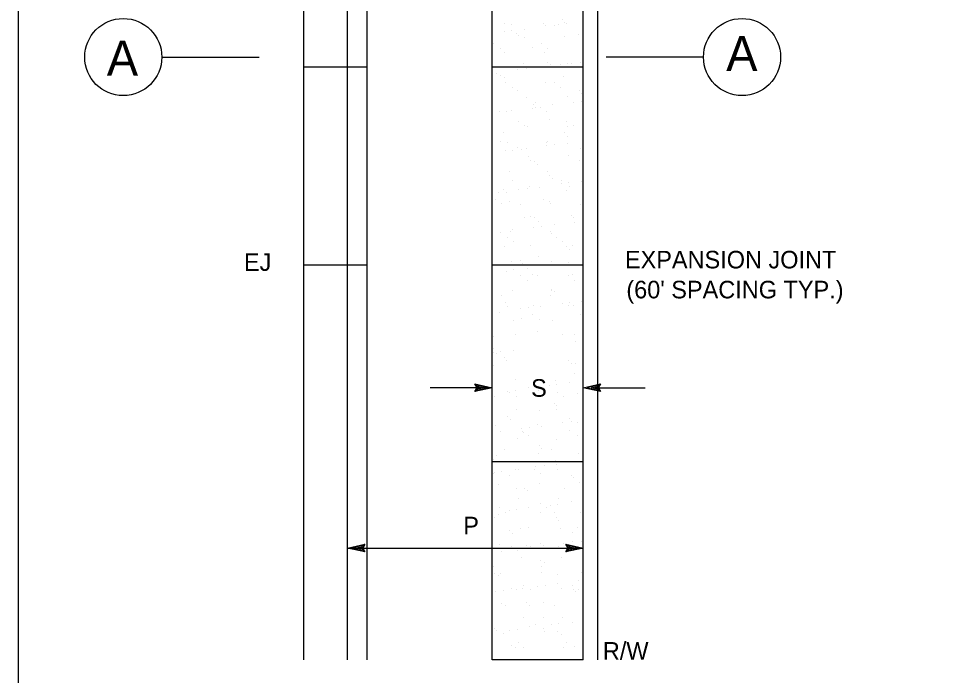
# Model space of a CAD drawing. Extents: x -118779 to -116979, y -104389 to -102939.
# Drawn here: x -118779.4 to -118463.7, y -103797.3 to -103572.9 of the extents above; entities that cross this region are included whole.
import ezdxf

# ---------------------------------------------------------------- set-up
doc = ezdxf.new("R2010")
doc.units = 0
for name, color, linetype in [('Default', 7, 'Continuous'), ('G-MARK', 7, 'Continuous'), ('G-TEXT', 7, 'Continuous'), ('Misc CnstDet(22)', 7, 'Continuous')]:
    doc.layers.add(name, color=color, linetype=linetype)

msp = doc.modelspace()

# ---------------------------------------------------------------- linework, layer by layer
at = {"layer": 'Default'}
msp.add_lwpolyline([(-118779.39, -102939.25), (-116979.39, -102939.25), (-116979.39, -104389.25), (-118779.39, -104389.25)], close=True, dxfattribs=at)
at = {"layer": 'G-MARK'}
for p, q in [((-118730.4, -103586.19), (-118697.22, -103586.19)), ((-118545.41, -103586.19), (-118578.59, -103586.19)), ((-118617.58, -103699.01), (-118638.74, -103699.01)), ((-118581.5, -103699.01), (-118565.32, -103699.01)), ((-118666.94, -103753.76), (-118586.48, -103753.76))]:
    msp.add_line(p, q, dxfattribs=at)
for centre in [(-118743.6, -103586.11), (-118532.21, -103586.11)]:
    msp.add_circle(centre, 13.17, dxfattribs=at)
at = {"layer": 'G-TEXT'}
for points in [[(-118623.49, -103697.69), (-118617.58, -103699.01), (-118623.49, -103700.32), (-118623.28, -103699.97), (-118618.95, -103699.01), (-118623.28, -103698.04), (-118623.07, -103698.39), (-118620.3, -103699.01), (-118623.07, -103699.62), (-118622.86, -103699.27), (-118621.66, -103699.01), (-118622.86, -103698.74), (-118622.7, -103699.01), (-118623.49, -103700.32), (-118622.7, -103699.01)], [(-118580.57, -103700.33), (-118586.48, -103699.01), (-118580.57, -103697.7), (-118580.78, -103698.05), (-118585.11, -103699.01), (-118580.78, -103699.98), (-118580.99, -103699.63), (-118583.76, -103699.01), (-118580.99, -103698.4), (-118581.2, -103698.75), (-118582.4, -103699.01), (-118581.2, -103699.28), (-118581.36, -103699.01), (-118580.57, -103697.7), (-118581.36, -103699.01)], [(-118661.03, -103755.08), (-118666.94, -103753.76), (-118661.03, -103752.45), (-118661.24, -103752.8), (-118665.57, -103753.76), (-118661.24, -103754.73), (-118661.45, -103754.38), (-118664.22, -103753.76), (-118661.45, -103753.15), (-118661.66, -103753.5), (-118662.86, -103753.76), (-118661.66, -103754.03), (-118661.82, -103753.76), (-118661.03, -103752.45), (-118661.82, -103753.76)], [(-118592.38, -103752.44), (-118586.48, -103753.76), (-118592.38, -103755.07), (-118592.17, -103754.72), (-118587.84, -103753.76), (-118592.17, -103752.79), (-118591.96, -103753.14), (-118589.19, -103753.76), (-118591.96, -103754.37), (-118591.75, -103754.02), (-118590.55, -103753.76), (-118591.76, -103753.49), (-118591.59, -103753.76), (-118592.38, -103755.07), (-118591.59, -103753.76)]]:
    msp.add_lwpolyline(points, close=True, dxfattribs=at)
at = {"layer": 'Misc CnstDet(22)'}
for p, q in [((-118593.53, -103573.34), (-118593.53, -103573.34)), ((-118613.43, -103574.58), (-118613.43, -103574.58)), ((-118610.95, -103575), (-118610.95, -103575)), ((-118606.38, -103576.66), (-118606.38, -103576.66)), ((-118600.16, -103574.58), (-118600.16, -103574.58)), ((-118599.33, -103575.41), (-118599.33, -103575.41)), ((-118596.43, -103575.41), (-118596.43, -103575.41)), ((-118594.77, -103575), (-118594.77, -103575)), ((-118592.7, -103574.17), (-118592.7, -103574.17)), ((-118592.28, -103574.58), (-118592.28, -103574.58)), ((-118613.43, -103577.48), (-118613.43, -103577.48)), ((-118610.95, -103577.07), (-118610.95, -103577.07)), ((-118609.29, -103577.9), (-118609.29, -103577.9)), ((-118608.46, -103578.73), (-118608.46, -103578.73)), ((-118606.38, -103579.56), (-118606.38, -103579.56)), ((-118592.7, -103579.14), (-118592.7, -103579.14)), ((-118588.13, -103578.31), (-118588.13, -103578.31)), ((-118617.17, -103581.63), (-118617.17, -103581.63)), ((-118603.9, -103582.88), (-118603.9, -103582.88)), ((-118600.58, -103581.63), (-118600.58, -103581.63)), ((-118614.68, -103583.29), (-118614.68, -103583.29)), ((-118613.43, -103584.54), (-118613.43, -103584.54)), ((-118599.75, -103584.54), (-118599.75, -103584.54)), ((-118598.5, -103583.29), (-118598.5, -103583.29)), ((-118606.8, -103588.27), (-118606.8, -103588.27)), ((-118598.5, -103587.85), (-118598.5, -103587.85)), ((-118597.67, -103588.68), (-118597.67, -103588.68)), ((-118594.36, -103588.68), (-118594.36, -103588.68)), ((-118591.87, -103588.27), (-118591.87, -103588.27)), ((-118590.62, -103588.27), (-118590.62, -103588.27)), ((-118587.3, -103587.85), (-118587.3, -103587.85)), ((-118660.3, -103589.51), (-118681.87, -103589.51)), ((-118586.48, -103589.51), (-118617.58, -103589.51)), ((-118615.92, -103591.59), (-118615.92, -103591.59)), ((-118614.68, -103592.42), (-118614.68, -103592.42)), ((-118608.87, -103590.34), (-118608.87, -103590.34)), ((-118605.97, -103589.51), (-118605.97, -103589.51)), ((-118605.97, -103589.93), (-118605.97, -103589.93)), ((-118601.82, -103589.51), (-118601.82, -103589.51)), ((-118592.28, -103589.51), (-118592.28, -103589.51)), ((-118613.43, -103593.25), (-118613.43, -103593.25)), ((-118613.02, -103594.9), (-118613.02, -103594.9)), ((-118613.02, -103594.9), (-118613.02, -103594.9)), ((-118599.33, -103594.9), (-118599.33, -103594.9)), ((-118596.43, -103594.9), (-118596.43, -103594.9)), ((-118593.11, -103592.83), (-118593.11, -103592.83)), ((-118610.53, -103596.56), (-118610.53, -103596.56)), ((-118608.87, -103597.39), (-118608.87, -103597.39)), ((-118594.36, -103596.56), (-118594.36, -103596.56)), ((-118587.72, -103597.39), (-118587.72, -103597.39)), ((-118586.89, -103598.64), (-118586.89, -103598.64)), ((-118605.97, -103599.88), (-118605.97, -103599.88)), ((-118602.65, -103601.54), (-118602.65, -103601.54)), ((-118591.87, -103599.47), (-118591.87, -103599.47)), ((-118589.79, -103601.54), (-118589.79, -103601.54)), ((-118586.89, -103601.13), (-118586.89, -103601.13)), ((-118615.09, -103604.86), (-118615.09, -103604.86)), ((-118612.61, -103604.86), (-118612.61, -103604.86)), ((-118610.95, -103604.44), (-118610.95, -103604.44)), ((-118603.9, -103603.61), (-118603.9, -103603.61)), ((-118603.48, -103602.37), (-118603.48, -103602.37)), ((-118602.65, -103603.2), (-118602.65, -103603.2)), ((-118600.99, -103603.2), (-118600.99, -103603.2)), ((-118598.92, -103604.86), (-118598.92, -103604.86)), ((-118596.84, -103602.37), (-118596.84, -103602.37)), ((-118608.46, -103608.18), (-118608.46, -103608.18)), ((-118598.09, -103607.35), (-118598.09, -103607.35)), ((-118592.28, -103608.18), (-118592.28, -103608.18)), ((-118606.38, -103609.42), (-118606.38, -103609.42)), ((-118605.55, -103609.84), (-118605.55, -103609.84)), ((-118591.87, -103609.84), (-118591.87, -103609.84)), ((-118589.79, -103609.42), (-118589.79, -103609.42)), ((-118613.85, -103611.91), (-118613.85, -103611.91)), ((-118592.7, -103611.91), (-118592.7, -103611.91)), ((-118591.87, -103613.15), (-118591.87, -103613.15)), ((-118614.68, -103614.81), (-118614.68, -103614.81)), ((-118612.19, -103615.23), (-118612.19, -103615.23)), ((-118608.87, -103616.89), (-118608.87, -103616.89)), ((-118607.63, -103617.72), (-118607.63, -103617.72)), ((-118605.97, -103617.3), (-118605.97, -103617.3)), ((-118598.92, -103615.23), (-118598.92, -103615.23)), ((-118598.92, -103616.47), (-118598.92, -103616.47)), ((-118598.5, -103614.81), (-118598.5, -103614.81)), ((-118596.43, -103616.06), (-118596.43, -103616.06)), ((-118591.87, -103615.64), (-118591.87, -103615.64)), ((-118587.3, -103617.3), (-118587.3, -103617.3)), ((-118613.02, -103618.13), (-118613.02, -103618.13)), ((-118610.53, -103618.13), (-118610.53, -103618.13)), ((-118605.14, -103620.21), (-118605.14, -103620.21)), ((-118591.45, -103619.79), (-118591.45, -103619.79)), ((-118604.31, -103621.45), (-118604.31, -103621.45)), ((-118603.07, -103621.86), (-118603.07, -103621.86)), ((-118602.24, -103622.69), (-118602.24, -103622.69)), ((-118587.72, -103621.45), (-118587.72, -103621.45)), ((-118611.78, -103625.18), (-118611.78, -103625.18)), ((-118598.5, -103625.18), (-118598.5, -103625.18)), ((-118598.09, -103626.43), (-118598.09, -103626.43)), ((-118610.53, -103628.09), (-118610.53, -103628.09)), ((-118604.72, -103630.16), (-118604.72, -103630.16)), ((-118596.84, -103627.67), (-118596.84, -103627.67)), ((-118593.94, -103628.09), (-118593.94, -103628.09)), ((-118593.94, -103629.33), (-118593.94, -103629.33)), ((-118591.45, -103628.92), (-118591.45, -103628.92)), ((-118591.04, -103630.16), (-118591.04, -103630.16)), ((-118586.89, -103628.5), (-118586.89, -103628.5)), ((-118615.51, -103632.23), (-118615.51, -103632.23)), ((-118613.85, -103631.4), (-118613.85, -103631.4)), ((-118612.61, -103632.23), (-118612.61, -103632.23)), ((-118608.46, -103631.4), (-118608.46, -103631.4)), ((-118605.55, -103630.99), (-118605.55, -103630.99)), ((-118601.41, -103630.57), (-118601.41, -103630.57)), ((-118592.28, -103631.82), (-118592.28, -103631.82)), ((-118616.34, -103634.72), (-118616.34, -103634.72)), ((-118614.26, -103635.97), (-118614.26, -103635.97)), ((-118611.78, -103635.55), (-118611.78, -103635.55)), ((-118608.04, -103636.38), (-118608.04, -103636.38)), ((-118600.16, -103634.72), (-118600.16, -103634.72)), ((-118598.09, -103635.55), (-118598.09, -103635.55)), ((-118597.67, -103635.97), (-118597.67, -103635.97)), ((-118587.3, -103636.38), (-118587.3, -103636.38)), ((-118606.38, -103640.94), (-118606.38, -103640.94)), ((-118604.31, -103640.53), (-118604.31, -103640.53)), ((-118603.07, -103640.94), (-118603.07, -103640.94)), ((-118601.82, -103642.19), (-118601.82, -103642.19)), ((-118590.62, -103640.11), (-118590.62, -103640.11)), ((-118589.79, -103640.94), (-118589.79, -103640.94)), ((-118589.38, -103642.6), (-118589.38, -103642.6)), ((-118586.48, -103642.19), (-118586.48, -103642.19)), ((-118614.68, -103645.92), (-118614.68, -103645.92)), ((-118611.36, -103645.51), (-118611.36, -103645.51)), ((-118610.53, -103645.09), (-118610.53, -103645.09)), ((-118603.48, -103644.26), (-118603.48, -103644.26)), ((-118600.58, -103643.85), (-118600.58, -103643.85)), ((-118597.67, -103645.51), (-118597.67, -103645.51)), ((-118596.43, -103643.43), (-118596.43, -103643.43)), ((-118612.19, -103647.58), (-118612.19, -103647.58)), ((-118610.12, -103649.24), (-118610.12, -103649.24)), ((-118597.26, -103646.34), (-118597.26, -103646.34)), ((-118595.6, -103647.58), (-118595.6, -103647.58)), ((-118593.53, -103649.24), (-118593.53, -103649.24)), ((-118613.43, -103650.9), (-118613.43, -103650.9)), ((-118604.31, -103650.48), (-118604.31, -103650.48)), ((-118592.28, -103650.9), (-118592.28, -103650.9)), ((-118591.04, -103651.73), (-118591.04, -103651.73)), ((-118590.21, -103650.48), (-118590.21, -103650.48)), ((-118608.04, -103655.46), (-118608.04, -103655.46)), ((-118601.82, -103654.22), (-118601.82, -103654.22)), ((-118660.3, -103657.12), (-118681.87, -103657.12)), ((-118586.48, -103657.12), (-118617.58, -103657.12)), ((-118610.95, -103655.87), (-118610.95, -103655.87)), ((-118610.12, -103658.78), (-118610.12, -103658.78)), ((-118607.21, -103656.7), (-118607.21, -103656.7)), ((-118605.55, -103658.36), (-118605.55, -103658.36)), ((-118598.5, -103657.12), (-118598.5, -103657.12)), ((-118597.26, -103655.87), (-118597.26, -103655.87)), ((-118596.01, -103657.12), (-118596.01, -103657.12)), ((-118591.45, -103656.29), (-118591.45, -103656.29)), ((-118586.48, -103656.29), (-118586.48, -103656.29)), ((-118612.61, -103659.19), (-118612.61, -103659.19)), ((-118608.04, -103660.85), (-118608.04, -103660.85)), ((-118603.9, -103660.44), (-118603.9, -103660.44)), ((-118602.24, -103660.85), (-118602.24, -103660.85)), ((-118591.45, -103660.85), (-118591.45, -103660.85)), ((-118590.21, -103660.44), (-118590.21, -103660.44)), ((-118605.55, -103662.51), (-118605.55, -103662.51)), ((-118589.38, -103662.51), (-118589.38, -103662.51)), ((-118614.26, -103667.49), (-118614.26, -103667.49)), ((-118610.53, -103665.83), (-118610.53, -103665.83)), ((-118597.67, -103667.49), (-118597.67, -103667.49)), ((-118597.26, -103665.41), (-118597.26, -103665.41)), ((-118597.26, -103665.83), (-118597.26, -103665.83)), ((-118596.43, -103666.24), (-118596.43, -103666.24)), ((-118613.02, -103669.98), (-118613.02, -103669.98)), ((-118612.19, -103671.22), (-118612.19, -103671.22)), ((-118603.48, -103670.81), (-118603.48, -103670.81)), ((-118600.99, -103671.22), (-118600.99, -103671.22)), ((-118593.53, -103670.39), (-118593.53, -103670.39)), ((-118591.45, -103670.81), (-118591.45, -103670.81)), ((-118591.04, -103669.98), (-118591.04, -103669.98)), ((-118589.79, -103670.81), (-118589.79, -103670.81)), ((-118586.89, -103669.56), (-118586.89, -103669.56)), ((-118615.09, -103673.29), (-118615.09, -103673.29)), ((-118608.04, -103672.05), (-118608.04, -103672.05)), ((-118605.14, -103671.64), (-118605.14, -103671.64)), ((-118603.9, -103674.12), (-118603.9, -103674.12)), ((-118587.3, -103674.12), (-118587.3, -103674.12)), ((-118610.12, -103676.2), (-118610.12, -103676.2)), ((-118607.63, -103675.37), (-118607.63, -103675.37)), ((-118601.41, -103675.78), (-118601.41, -103675.78)), ((-118596.84, -103676.2), (-118596.84, -103676.2)), ((-118586.48, -103675.37), (-118586.48, -103675.37)), ((-118609.7, -103680.76), (-118609.7, -103680.76)), ((-118602.24, -103679.93), (-118602.24, -103679.93)), ((-118593.53, -103680.76), (-118593.53, -103680.76)), ((-118589.38, -103680.76), (-118589.38, -103680.76)), ((-118617.17, -103681.59), (-118617.17, -103681.59)), ((-118588.96, -103683.25), (-118588.96, -103683.25)), ((-118617.17, -103685.74), (-118617.17, -103685.74)), ((-118617.17, -103686.98), (-118617.17, -103686.98)), ((-118614.68, -103686.57), (-118614.68, -103686.57)), ((-118610.12, -103686.15), (-118610.12, -103686.15)), ((-118610.12, -103686.15), (-118610.12, -103686.15)), ((-118617.58, -103697.35), (-118617.58, -103688.23)), ((-118615.92, -103687.4), (-118615.92, -103687.4)), ((-118613.43, -103688.64), (-118613.43, -103688.64)), ((-118612.61, -103689.89), (-118612.61, -103689.89)), ((-118591.45, -103689.89), (-118591.45, -103689.89)), ((-118586.48, -103697.35), (-118586.48, -103688.23)), ((-118617.17, -103691.54), (-118617.17, -103691.54)), ((-118590.62, -103690.72), (-118590.62, -103690.72)), ((-118588.96, -103690.72), (-118588.96, -103690.72)), ((-118609.7, -103696.11), (-118609.7, -103696.11)), ((-118596.01, -103696.52), (-118596.01, -103696.52)), ((-118589.38, -103694.03), (-118589.38, -103694.03)), ((-118609.7, -103699.84), (-118609.7, -103699.84)), ((-118605.14, -103699.01), (-118605.14, -103699.01)), ((-118601.82, -103699.84), (-118601.82, -103699.84)), ((-118598.09, -103698.18), (-118598.09, -103698.18)), ((-118595.6, -103697.77), (-118595.6, -103697.77)), ((-118591.04, -103697.35), (-118591.04, -103697.35)), ((-118586.48, -103699.01), (-118586.48, -103699.01)), ((-118617.58, -103701.08), (-118617.58, -103701.08)), ((-118616.75, -103701.91), (-118616.75, -103701.91)), ((-118612.19, -103700.25), (-118612.19, -103700.25)), ((-118611.78, -103700.67), (-118611.78, -103700.67)), ((-118609.29, -103701.91), (-118609.29, -103701.91)), ((-118602.65, -103701.08), (-118602.65, -103701.08)), ((-118595.19, -103700.67), (-118595.19, -103700.67)), ((-118593.11, -103701.91), (-118593.11, -103701.91)), ((-118588.55, -103701.08), (-118588.55, -103701.08)), ((-118586.48, -103701.08), (-118586.48, -103701.08)), ((-118617.58, -103704.4), (-118617.58, -103704.4)), ((-118596.43, -103704.4), (-118596.43, -103704.4)), ((-118595.6, -103705.23), (-118595.6, -103705.23)), ((-118612.19, -103708.96), (-118612.19, -103708.96)), ((-118609.29, -103706.48), (-118609.29, -103706.48)), ((-118601.41, -103706.89), (-118601.41, -103706.89)), ((-118595.6, -103706.48), (-118595.6, -103706.48)), ((-118591.04, -103709.38), (-118591.04, -103709.38)), ((-118616.34, -103711.87), (-118616.34, -103711.87)), ((-118611.36, -103709.79), (-118611.36, -103709.79)), ((-118602.24, -103711.45), (-118602.24, -103711.45)), ((-118600.58, -103712.28), (-118600.58, -103712.28)), ((-118593.53, -103711.04), (-118593.53, -103711.04)), ((-118590.62, -103710.62), (-118590.62, -103710.62)), ((-118588.55, -103711.04), (-118588.55, -103711.04)), ((-118586.48, -103710.21), (-118586.48, -103710.21)), ((-118614.68, -103713.94), (-118614.68, -103713.94)), ((-118607.63, -103713.11), (-118607.63, -103713.11)), ((-118607.21, -103713.94), (-118607.21, -103713.94)), ((-118606.8, -103714.36), (-118606.8, -103714.36)), ((-118605.14, -103715.19), (-118605.14, -103715.19)), ((-118604.72, -103712.7), (-118604.72, -103712.7)), ((-118591.04, -103713.53), (-118591.04, -103713.53)), ((-118588.55, -103715.19), (-118588.55, -103715.19)), ((-118608.87, -103716.43), (-118608.87, -103716.43)), ((-118595.6, -103716.85), (-118595.6, -103716.85)), ((-118613.43, -103720.16), (-118613.43, -103720.16)), ((-118601.82, -103721.41), (-118601.82, -103721.41)), ((-118601.41, -103718.92), (-118601.41, -103718.92)), ((-118600.58, -103719.75), (-118600.58, -103719.75)), ((-118597.26, -103720.16), (-118597.26, -103720.16)), ((-118588.13, -103721.41), (-118588.13, -103721.41)), ((-118586.48, -103724.31), (-118617.58, -103724.31)), ((-118617.17, -103723.48), (-118617.17, -103723.48)), ((-118616.34, -103724.31), (-118616.34, -103724.31)), ((-118615.92, -103722.24), (-118615.92, -103722.24)), ((-118596.01, -103723.9), (-118596.01, -103723.9)), ((-118595.6, -103725.14), (-118595.6, -103725.14)), ((-118588.55, -103724.31), (-118588.55, -103724.31)), ((-118616.75, -103728.04), (-118616.75, -103728.04)), ((-118614.26, -103727.63), (-118614.26, -103727.63)), ((-118609.7, -103726.8), (-118609.7, -103726.8)), ((-118608.46, -103726.8), (-118608.46, -103726.8)), ((-118603.07, -103726.8), (-118603.07, -103726.8)), ((-118602.65, -103725.97), (-118602.65, -103725.97)), ((-118599.75, -103725.56), (-118599.75, -103725.56)), ((-118595.19, -103726.8), (-118595.19, -103726.8)), ((-118586.48, -103726.8), (-118586.48, -103726.8)), ((-118617.17, -103728.46), (-118617.17, -103728.46)), ((-118611.78, -103728.87), (-118611.78, -103728.87)), ((-118600.99, -103728.46), (-118600.99, -103728.46)), ((-118590.62, -103728.87), (-118590.62, -103728.87)), ((-118589.79, -103729.7), (-118589.79, -103729.7)), ((-118587.72, -103731.36), (-118587.72, -103731.36)), ((-118615.51, -103732.19), (-118615.51, -103732.19)), ((-118609.29, -103733.44), (-118609.29, -103733.44)), ((-118606.38, -103733.44), (-118606.38, -103733.44)), ((-118605.55, -103734.27), (-118605.55, -103734.27)), ((-118601.41, -103731.78), (-118601.41, -103731.78)), ((-118592.7, -103733.44), (-118592.7, -103733.44)), ((-118608.46, -103736.75), (-118608.46, -103736.75)), ((-118594.77, -103736.75), (-118594.77, -103736.75)), ((-118615.09, -103740.07), (-118615.09, -103740.07)), ((-118611.78, -103740.9), (-118611.78, -103740.9)), ((-118609.29, -103740.49), (-118609.29, -103740.49)), ((-118605.14, -103740.07), (-118605.14, -103740.07)), ((-118600.99, -103738.41), (-118600.99, -103738.41)), ((-118598.92, -103740.07), (-118598.92, -103740.07)), ((-118597.67, -103739.24), (-118597.67, -103739.24)), ((-118595.19, -103738.83), (-118595.19, -103738.83)), ((-118590.62, -103738), (-118590.62, -103738)), ((-118666.94, -103752.93), (-118666.94, -103743.39)), ((-118616.75, -103743.39), (-118616.75, -103743.39)), ((-118615.51, -103742.15), (-118615.51, -103742.15)), ((-118613.02, -103741.73), (-118613.02, -103741.73)), ((-118600.99, -103741.73), (-118600.99, -103741.73)), ((-118596.43, -103741.73), (-118596.43, -103741.73)), ((-118595.6, -103743.39), (-118595.6, -103743.39)), ((-118587.3, -103741.73), (-118587.3, -103741.73)), ((-118586.48, -103752.93), (-118586.48, -103743.39)), ((-118608.04, -103747.12), (-118608.04, -103747.12)), ((-118605.14, -103746.71), (-118605.14, -103746.71)), ((-118594.77, -103744.22), (-118594.77, -103744.22)), ((-118594.36, -103747.12), (-118594.36, -103747.12)), ((-118588.55, -103746.71), (-118588.55, -103746.71)), ((-118611.78, -103747.95), (-118611.78, -103747.95)), ((-118610.53, -103748.78), (-118610.53, -103748.78)), ((-118590.21, -103748.37), (-118590.21, -103748.37)), ((-118615.09, -103752.51), (-118615.09, -103752.51)), ((-118610.95, -103753.34), (-118610.95, -103753.34)), ((-118605.97, -103752.93), (-118605.97, -103752.93)), ((-118604.31, -103753.34), (-118604.31, -103753.34)), ((-118600.99, -103752.1), (-118600.99, -103752.1)), ((-118600.16, -103752.93), (-118600.16, -103752.93)), ((-118594.77, -103753.34), (-118594.77, -103753.34)), ((-118593.11, -103752.1), (-118593.11, -103752.1)), ((-118590.21, -103751.69), (-118590.21, -103751.69)), ((-118586.89, -103751.69), (-118586.89, -103751.69)), ((-118666.94, -103756.66), (-118666.94, -103756.66)), ((-118614.26, -103755), (-118614.26, -103755)), ((-118608.87, -103754.59), (-118608.87, -103754.59)), ((-118607.21, -103753.76), (-118607.21, -103753.76)), ((-118592.28, -103754.59), (-118592.28, -103754.59)), ((-118586.48, -103753.76), (-118586.48, -103753.76)), ((-118586.48, -103756.66), (-118586.48, -103756.66)), ((-118607.63, -103757.08), (-118607.63, -103757.08)), ((-118600.99, -103757.91), (-118600.99, -103757.91)), ((-118599.75, -103758.74), (-118599.75, -103758.74)), ((-118593.94, -103757.08), (-118593.94, -103757.08)), ((-118617.17, -103759.98), (-118617.17, -103759.98)), ((-118616.75, -103762.47), (-118616.75, -103762.47)), ((-118614.68, -103762.47), (-118614.68, -103762.47)), ((-118600.58, -103759.98), (-118600.58, -103759.98)), ((-118600.58, -103762.05), (-118600.58, -103762.05)), ((-118595.19, -103762.88), (-118595.19, -103762.88)), ((-118586.89, -103762.05), (-118586.89, -103762.05)), ((-118615.51, -103763.3), (-118615.51, -103763.3)), ((-118595.19, -103765.79), (-118595.19, -103765.79)), ((-118588.13, -103764.96), (-118588.13, -103764.96)), ((-118616.34, -103768.69), (-118616.34, -103768.69)), ((-118613.85, -103768.28), (-118613.85, -103768.28)), ((-118610.95, -103767.45), (-118610.95, -103767.45)), ((-118609.29, -103767.86), (-118609.29, -103767.86)), ((-118607.21, -103767.45), (-118607.21, -103767.45)), ((-118606.8, -103766.62), (-118606.8, -103766.62)), ((-118604.31, -103767.86), (-118604.31, -103767.86)), ((-118602.24, -103767.03), (-118602.24, -103767.03)), ((-118599.33, -103766.62), (-118599.33, -103766.62)), ((-118593.94, -103767.45), (-118593.94, -103767.45)), ((-118590.21, -103766.62), (-118590.21, -103766.62)), ((-118589.79, -103767.86), (-118589.79, -103767.86)), ((-118588.96, -103768.69), (-118588.96, -103768.69)), ((-118588.13, -103767.86), (-118588.13, -103767.86)), ((-118605.97, -103772.42), (-118605.97, -103772.42)), ((-118600.16, -103772.42), (-118600.16, -103772.42)), ((-118586.48, -103772.01), (-118586.48, -103772.01)), ((-118614.26, -103772.84), (-118614.26, -103772.84)), ((-118613.02, -103773.25), (-118613.02, -103773.25)), ((-118604.72, -103773.25), (-118604.72, -103773.25)), ((-118596.43, -103773.25), (-118596.43, -103773.25)), ((-118606.8, -103777.4), (-118606.8, -103777.4)), ((-118600.16, -103777.4), (-118600.16, -103777.4)), ((-118593.53, -103777.4), (-118593.53, -103777.4)), ((-118616.75, -103781.13), (-118616.75, -103781.13)), ((-118615.92, -103781.96), (-118615.92, -103781.96)), ((-118611.78, -103781.96), (-118611.78, -103781.96)), ((-118608.87, -103781.55), (-118608.87, -103781.55)), ((-118604.72, -103780.72), (-118604.72, -103780.72)), ((-118602.65, -103779.89), (-118602.65, -103779.89)), ((-118600.16, -103781.13), (-118600.16, -103781.13)), ((-118597.26, -103779.89), (-118597.26, -103779.89)), ((-118594.77, -103779.47), (-118594.77, -103779.47)), ((-118590.21, -103779.06), (-118590.21, -103779.06)), ((-118613.85, -103782.79), (-118613.85, -103782.79)), ((-118599.75, -103782.38), (-118599.75, -103782.38)), ((-118595.19, -103782.38), (-118595.19, -103782.38)), ((-118593.94, -103783.21), (-118593.94, -103783.21)), ((-118610.95, -103786.94), (-118610.95, -103786.94)), ((-118609.7, -103787.77), (-118609.7, -103787.77)), ((-118608.46, -103786.11), (-118608.46, -103786.11)), ((-118606.8, -103787.77), (-118606.8, -103787.77)), ((-118593.11, -103787.77), (-118593.11, -103787.77)), ((-118592.28, -103786.11), (-118592.28, -103786.11)), ((-118589.38, -103787.36), (-118589.38, -103787.36)), ((-118586.48, -103791.92), (-118617.58, -103791.92))]:
    msp.add_line(p, q, dxfattribs=at)
for points in [[(-118581.5, -103791.92), (-118581.5, -103253.97), (-118455.82, -103128.71), (-118400.25, -103128.71)], [(-118681.87, -103791.92), (-118681.87, -103251.89)], [(-118666.94, -103791.92), (-118666.94, -103251.89)], [(-118660.3, -103791.92), (-118660.3, -103251.89)], [(-118617.58, -103791.92), (-118617.58, -103251.89)], [(-118586.48, -103791.92), (-118586.48, -103251.89)]]:
    msp.add_lwpolyline(points, dxfattribs=at)

# ---------------------------------------------------------------- texts
for s, height, p in [('A', 12, (-118537.63, -103590.89)), ('A', 12, (-118749.22, -103592.45)), ('EXPANSION JOINT', 6, (-118572.22, -103658.28)), ('EJ', 6, (-118702.36, -103659.12)), ("(60' SPACING TYP.)", 6, (-118571.74, -103668.51)), ('S', 6, (-118604.27, -103702.11)), ('P', 6, (-118627.44, -103749.1)), ('R/W', 6, (-118579.76, -103791.89))]:
    msp.add_text(s, height=height, dxfattribs=at).set_placement(p)

doc.saveas('drawing.dxf')
